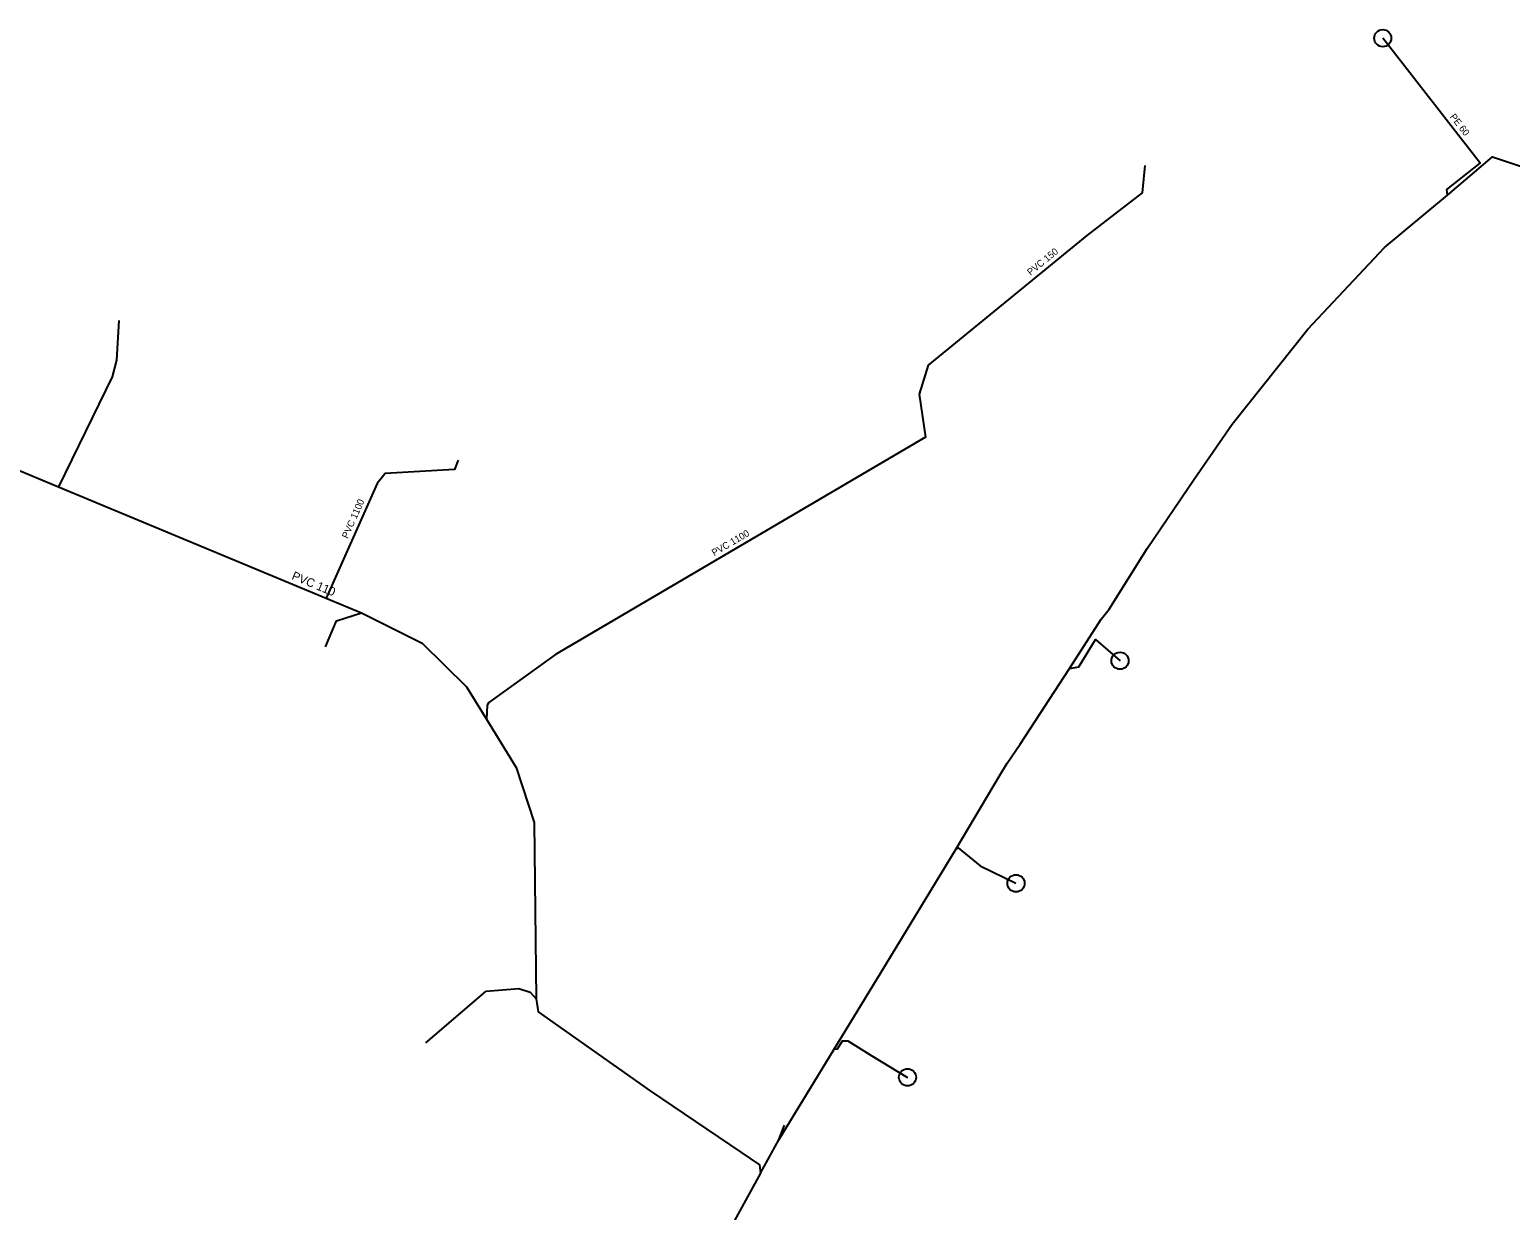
# Model space of a CAD drawing. Extents: x -687195 to -686827, y -1053873 to -1053627.
# Drawn here: x -687097.1 to -687010.4, y -1053803.5 to -1053734.4 of the extents above; entities that cross this region are included whole.
import ezdxf

# ---------------------------------------------------------------- set-up
doc = ezdxf.new("R2010")
doc.units = 0
for name, color, linetype in [('Kanalizační přípojky', 7, 'Continuous'), ('Kanalizační stoka', 7, 'Continuous'), ('Kanalizační šachty', 7, 'Continuous'), ('Popis', 7, 'Continuous')]:
    doc.layers.add(name, color=color, linetype=linetype)

msp = doc.modelspace()

# ---------------------------------------------------------------- linework, layer by layer
at = {"layer": 'Kanalizační přípojky'}
for points in [[(-687014.12, -1053744.08), (-687014.15, -1053743.76), (-687012.21, -1053742.21), (-687017.91, -1053734.89)], [(-687031.84, -1053742.35), (-687032, -1053743.95), (-687035.24, -1053746.44), (-687044.53, -1053754.04), (-687045.04, -1053755.74)], [(-687091.9, -1053751.42), (-687092.04, -1053753.75), (-687092.3, -1053754.71)], [(-687092.3, -1053754.71), (-687095.44, -1053761.16)], [(-687045.04, -1053755.74), (-687044.68, -1053758.25), (-687066.35, -1053770.98), (-687070.24, -1053773.79), (-687070.34, -1053773.95), (-687070.38, -1053774.76)], [(-687072.03, -1053759.59), (-687072.26, -1053760.15), (-687076.32, -1053760.38), (-687076.79, -1053760.96)], [(-687076.79, -1053760.96), (-687079.76, -1053767.68)], [(-687079.8, -1053770.52), (-687079.16, -1053769.01), (-687077.7, -1053768.54)], [(-687036.25, -1053771.79), (-687035.71, -1053771.69), (-687034.73, -1053770.09), (-687033.29, -1053771.34)], [(-687042.89, -1053782.36), (-687042.76, -1053782.29), (-687041.48, -1053783.34), (-687039.38, -1053784.37)], [(-687073.94, -1053793.71), (-687070.4, -1053790.68)], [(-687070.4, -1053790.68), (-687068.49, -1053790.53), (-687067.82, -1053790.75), (-687067.48, -1053791.14)], [(-687050.03, -1053794.09), (-687049.83, -1053794.07), (-687049.54, -1053793.59), (-687049.22, -1053793.59), (-687047.82, -1053794.48), (-687045.73, -1053795.73)]]:
    msp.add_lwpolyline(points, dxfattribs=at)
at = {"layer": 'Kanalizační stoka'}
for points in [[(-687054.34, -1053801.35), (-687053.26, -1053799.39), (-687050.03, -1053794.09), (-687047.27, -1053789.58), (-687042.89, -1053782.36), (-687040.34, -1053778.08), (-687039.9, -1053777.34), (-687039.13, -1053776.23), (-687036.25, -1053771.79), (-687034.4, -1053768.9), (-687033.93, -1053768.32), (-687031.7, -1053764.77), (-687028.94, -1053760.7), (-687026.73, -1053757.48), (-687022.29, -1053751.92), (-687017.81, -1053747.14), (-687014.12, -1053744.08), (-687011.48, -1053741.84), (-687009.38, -1053742.55)], [(-687124.62, -1053748), (-687120.35, -1053750.17), (-687109.72, -1053754.89), (-687098.15, -1053760.03), (-687095.44, -1053761.16), (-687079.76, -1053767.68), (-687077.7, -1053768.54), (-687074.14, -1053770.31), (-687071.55, -1053772.86), (-687070.39, -1053774.76), (-687068.65, -1053777.6), (-687067.59, -1053780.82), (-687067.48, -1053791.14), (-687067.36, -1053791.9), (-687060.79, -1053796.53), (-687055.49, -1053800.12)], [(-687053.26, -1053799.39), (-687052.94, -1053798.53)], [(-687055.49, -1053800.12), (-687054.39, -1053800.86), (-687054.34, -1053801.35)], [(-687054.34, -1053801.35), (-687058.71, -1053809.31), (-687061.25, -1053814.42), (-687063.24, -1053818.66)]]:
    msp.add_lwpolyline(points, dxfattribs=at)
at = {"layer": 'Kanalizační šachty'}
for centre in [(-687017.91, -1053734.89), (-687033.29, -1053771.34), (-687039.38, -1053784.37), (-687045.73, -1053795.73)]:
    msp.add_circle(centre, 0.5, dxfattribs=at)

# ---------------------------------------------------------------- texts
at = {"layer": 'Popis'}
for s, height, rotation, p in [('PE 60', 0.4, 307.90748, (-687014.001, -1053739.503)), ('PVC 150', 0.4, 39.28605, (-687038.526, -1053748.806)), ('PVC 1100', 0.4, 66.15628, (-687078.504, -1053764.219)), ('PVC 1100', 0.4, 30.43202, (-687057.048, -1053765.226)), ('PVC 110', 0.5, 337.42166, (-687081.825, -1053766.551))]:
    msp.add_text(s, height=height, rotation=rotation, dxfattribs=at).set_placement(p)

doc.saveas('drawing.dxf')
